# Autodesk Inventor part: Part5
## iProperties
Shininess: 77.0
Length Units: 11269
Angle Units: 11279
Time Units: 11290
Mass Units: 11283
Length Display Precision: 3
Angle Display Precision: 2
Created: 2002-01
Part Number: Part5
Document SubType Name: Modeling
Designer: ***
Density: 0.0
Volumn: 0.0
Area: 0.0
PropertySet Name: Model Information
Control State: 0
Master: False
Checked Out: False
Author: ***
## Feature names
1. Extrusion1
2. Extrusion2
3. Hole1
